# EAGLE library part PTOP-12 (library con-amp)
AMP connector
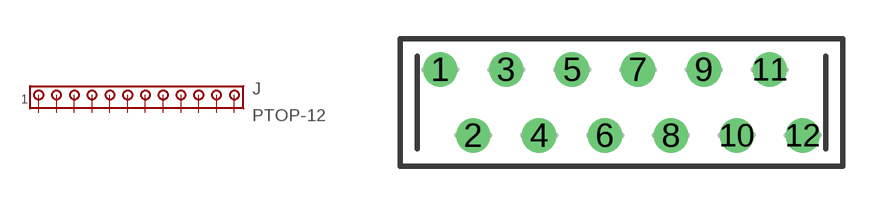
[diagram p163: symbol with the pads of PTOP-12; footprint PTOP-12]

Designator prefix J

## PTOP-12 (OC_FARNELL: unknown; OC_NEWARK: unknown)  [PTOP-12]
1  1  pas
2  2  pas
3  3  pas
4  4  pas
5  5  pas
6  6  pas
7  7  pas
8  8  pas
9  9  pas
10  10  pas
11  11  pas
12  12  pas

## Footprint PTOP-12 (pad centres in mm)
AMP connector
drill 0.813 round: 1 -6.985,1.27; 2 -5.715,-1.27; 3 -4.445,1.27; 4 -3.175,-1.27; 5 -1.905,1.27; 6 -0.635,-1.27; 7 0.635,1.27; 8 1.905,-1.27; 9 3.175,1.27; 10 4.445,-1.27; 11 5.715,1.27; 12 6.985,-1.27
